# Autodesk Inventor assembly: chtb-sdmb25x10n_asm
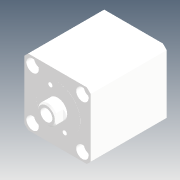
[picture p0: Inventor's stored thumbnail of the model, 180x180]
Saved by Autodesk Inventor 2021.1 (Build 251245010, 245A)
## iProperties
Company: Microsoft
Created: 2018-05
Part Number: chtb-sdmb25x10n_asm
Description: STEP AP214
Document SubType Name: Assembly
Designer: user
Title: chtb-sdmb25x10n_asm.STEP
Author: Windows
Revision Number: ÈÎºÎ
Sending System: SolidWorks 2015
Preprocessor: SwSTEP 2.0
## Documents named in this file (4)
- D:\Vault_2016\Projekty\Clamptek\Hydraulic\CHTB\CHTB-25\Inventor\chtb-sdmb25x10n\chtb-sdmb25x10n_asm.iam
- D:\Vault_2016\Projekty\Clamptek\Hydraulic\CHTB\CHTB-25\Inventor\chtb-sdmb25x10n\CHTB-SDMB25X10NBT.ipt
- D:\Vault_2016\Projekty\Clamptek\Hydraulic\CHTB\CHTB-25\Inventor\chtb-sdmb25x10n\CHTB-SDMB25X10NHSG.ipt
- D:\Vault_2016\Projekty\Clamptek\Hydraulic\CHTB\CHTB-25\Inventor\chtb-sdmb25x10n\CHTB-25QG.ipt
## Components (3 placed, 3 different names)
1. CHTB-SDMB25X10NBT_1
2. CHTB-SDMB25X10NHSG_2
3. CHTB-25QG_3
